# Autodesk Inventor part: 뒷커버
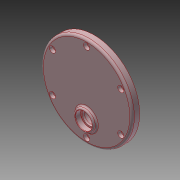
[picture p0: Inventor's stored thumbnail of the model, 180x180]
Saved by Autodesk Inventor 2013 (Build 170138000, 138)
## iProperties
Created: 2024-02
Part Number: 뒷커버
Material: 알루미늄 6061
Document SubType Name: Modeling
Designer: mdu-01
Density: 2.71 g/cm^3
Mass: 304.887 g
Surface Area: 294.624 cm^2
Volume: 112.504 cm^3
Author: mdu-01
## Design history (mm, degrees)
sketch "스케치1"
  geometry: C1 r 60 at (0, 0) reference; C2 r 44 at (0, 0) reference; C3 r 11 at (0, -31) reference; C4 r 11 at (0, 0) reference; C5 r 46 at (0, 0) reference; A1 r 41 centre (0, 0) between (20.39, -35.57) and (-20.39, -35.57); A2 r 16 centre (0, 0) between (9.254, -13.053) and (-9.254, -13.053); A3 r 16 centre (0, -31) between (15.914, -32.657) and (9.254, -17.947); A4 r 16 centre (0, -31) between (-9.254, -17.947) and (-15.914, -32.657); A5 r 3 centre (18.898, -32.968) between (15.914, -32.657) and (20.39, -35.57); A6 r 3 centre (-18.898, -32.968) between (-20.39, -35.57) and (-15.914, -32.657); A7 r 3 centre (-10.989, -15.5) between (-9.254, -17.947) and (-9.254, -13.053); A8 r 3 centre (10.989, -15.5) between (9.254, -13.053) and (9.254, -17.947); 1 further point
  constraints: 16 point on circle, 8 centre point, 8 tangent, 5 equal radius
  dimensions: "d2" = 5 radial gap between concentric circles of C4 A2; "d3" = 3 radius of A5; "d46" = 5 radial gap between concentric circles of C5 A1
  node "참조1"
  node "참조2"
  node "참조3"
  node "참조4"
  node "참조11"
extrude "돌출1" new body sketch "스케치1" distance "d4" = 10; taper "d5" = 0 deg
extrude "돌출2" join sketch "스케치1" distance "d6" = 3; taper "d7" = 0 deg
chamfer "모따기1" distance "d8" = 1; stored, may be unused: second distance "d9" = 2, angle "d10" = 45 deg
sketch "스케치2"
  geometry: C1 r 13.5 at (0, -31); A1 r 3.5 centre (0, -31) between (1, -34.354) and (-1, -34.354) reference; 1 further point
  constraints: 1 centre point
  dimensions: "d11" = 27 diameter of C1
extrude "돌출3" join sketch "스케치2" distance "d14" = 4; taper "d15" = 0 deg
fillet "모깎기1" dims "d16" = 3
sketch "스케치3"
  geometry: C1 r 1.621 at (0, 52) reference; 1 further point
hole "구멍1" sketch "스케치3" at (0, 52) diameter "d18" = 4.5; stored, may be unused: countersink angle "d22" = 90 deg, drill point angle "d24" = 118 deg; dims "d19" = 6, "d20" = 8, "d21" = 4.4, "d23" = 8
fillet "모깎기2" dims "d31" = 2
sketch "스케치4"
  geometry: L1 (11, 3.7)-(11, -2.7) reference; L2 (-10.7, 4)-(10.7, 4) reference; L3 (10.7, -3)-(-10.7, -3) reference; L4 (10.7, -3)-(11, -3); L5 (11, -3)-(11, -2.7); L6 (6, 7)-(0, 7); L7 (0, 7)-(0, -3); L8 (10.7, 4)-(9, 4); A1 r 0.3 centre (10.7, 3.7) between (11, 3.7) and (10.7, 4); A2 r 3 centre (6, 4) between (9, 4) and (6, 7); 1 further point
  constraints: 13 end point, 4 point on circle, 3 tangent, 2 centre point, 2 collinear, 2 perpendicular, 2 point on line, 1 midpoint, 1 vertical, 2 other
  dimensions: "d33" = 3 distance from line of L6.start L2; "d34" = 2 distance from line of L8.end L1
revolve "회전1" sketch "스케치4" stored, may be unused: angle "d35" = 90 deg
sketch "스케치5"
  geometry: L1 (-20.3, -3)-(-41.7, -3) reference; L2 (-20, 3.7)-(-20, -2.7) reference; L3 (-41.7, 4)-(-20.3, 4) reference; L4 (-42.5, 14)-(-19.5, 14) reference; L5 (-20.3, -3)-(-20, -3); L6 (-20, -3)-(-20, -2.7); L7 (-20.3, 4)-(-22, 4); L8 (-20, 13.3)-(-20, 7); L9 (-20.3, 6.7)-(-22, 6.7); L10 (-22, 6.7)-(-22, 4); L11 (-19.596, 14)-(-20, 13.3); L12 (-31, -3)-(-31, 14); A1 r 0.3 centre (-20.3, 3.7) between (-20, 3.7) and (-20.3, 4); A2 r 0.3 centre (-20.3, 7) between (-20.3, 6.7) and (-20, 7); 1 further point
  constraints: 18 end point, 4 point on circle, 3 perpendicular, 3 tangent, 2 centre point, 2 midpoint, 2 parallel, 2 point on line, 1 vertical, 2 other
  dimensions: "d36" = 7.3 distance between parallel lines of L9 L4; "d37" = 2 distance between parallel lines of L2 L10; "d38" = 0.7 distance from line of L8.start L4; "d39" = 30 deg angle of L8 L11; "d40" = 22 diameter of L8 L12; "d41" = 0.3 radius of A2
revolve "회전2" sketch "스케치5" stored, may be unused: angle "d42" = 90 deg
chamfer "모따기2" distance "d43" = 0.5; stored, may be unused: second distance "d44" = 2, angle "d45" = 45 deg
node "솔리드1"
pattern_circular "원형 패턴1" dims angle "d26" = 360 deg
node "참조5"
node "참조6"
node "참조7"
node "참조8"
node "참조9"
node "참조10"
other parameters: "d1" = 5
